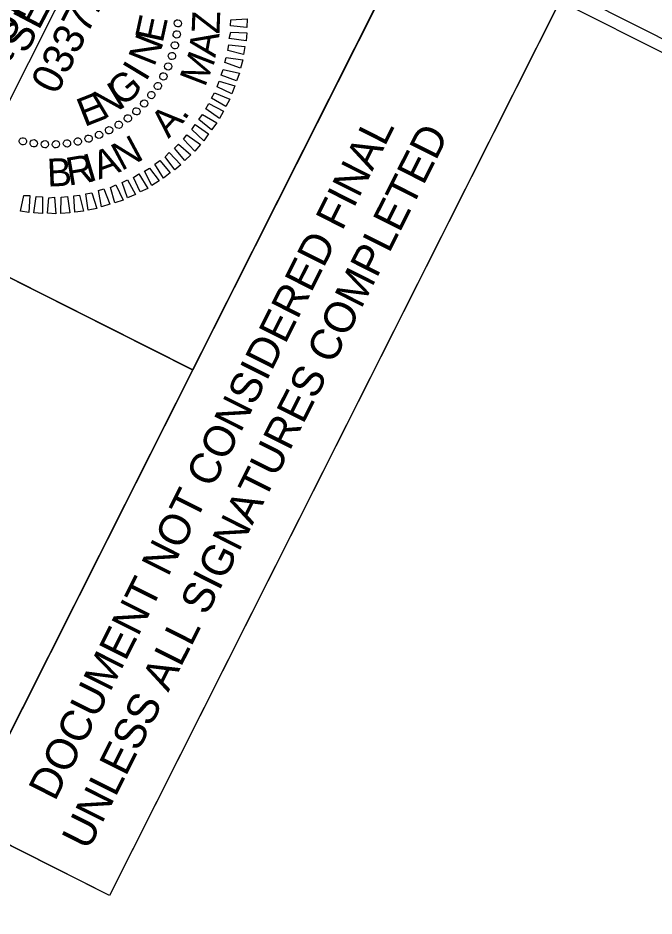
# Model space of a CAD drawing. Extents: x 2010322 to 2012069, y 441674 to 443687.
# Drawn here: x 2011152.3 to 2011277.9, y 443389 to 443566.2 of the extents above; entities that cross this region are included whole.
import ezdxf

# ---------------------------------------------------------------- set-up
doc = ezdxf.new("R2010")
doc.units = 0
for name, color, linetype in [('Sheet Clip Boundary CELL', 7, 'Continuous'), ('Sheet Plan And Profile CELL', 7, 'Continuous'), ('Sheet Professional Seal CELL', 7, 'Continuous'), ('Sheet Profile Grid Minor CELL', 7, 'Continuous'), ('Sheet Sticker Exception Certification CELL', 7, 'Continuous'), ('Sheet Sticker Incomplete CELL', 7, 'Continuous')]:
    doc.layers.add(name, color=color, linetype=linetype)

msp = doc.modelspace()

# ---------------------------------------------------------------- linework, layer by layer
at = {"layer": 'Sheet Clip Boundary CELL'}
msp.add_lwpolyline([(2011359.68, 441843.44), (2012033.06, 443180.92), (2011922.92, 443238.13), (2011759.16, 443078.9), (2011595.22, 443247.25), (2011606.93, 443258.94), (2011612.2, 443362.21), (2011388.82, 443474.46), (2011348.46, 443524.76), (2011259.26, 443569.48), (2011170.42, 443393.01), (2011067.41, 443444.87), (2010977.45, 443266.18), (2010917.88, 443296.17), (2010676.94, 442817.58), (2010544.65, 442554.81), (2010423.28, 442313.75), (2010551.1, 442249.4)], close=True, dxfattribs=at)
at = {"layer": 'Sheet Plan And Profile CELL'}
msp.add_line((2011086.37, 443547.34), (2011186.81, 443496.77), dxfattribs=at)
for points in [[(2011097.8, 443653.54), (2010423.28, 442313.75), (2011361.14, 441841.59), (2012035.65, 443181.38)], [(2011086.37, 443547.34), (2011131.34, 443636.65), (2011231.82, 443586.07), (2011186.86, 443496.75)], [(2011041.38, 443457.97), (2011086.37, 443547.34), (2011186.86, 443496.75), (2011141.87, 443407.38)]]:
    msp.add_lwpolyline(points, close=True, dxfattribs=at)
at = {"layer": 'Sheet Professional Seal CELL'}
for p, q in [((2011183.92, 443565.1), (2011183.92, 443565.1)), ((2011183.74, 443562.96), (2011183.74, 443562.96)), ((2011183.33, 443560.81), (2011183.33, 443560.81)), ((2011182.7, 443558.67), (2011182.7, 443558.67)), ((2011182, 443556.61), (2011182, 443556.61)), ((2011181.05, 443554.62), (2011181.05, 443554.62)), ((2011179.93, 443552.73), (2011179.93, 443552.73)), ((2011178.65, 443550.96), (2011178.65, 443550.96)), ((2011177.31, 443549.29), (2011177.31, 443549.29)), ((2011175.74, 443547.73), (2011175.74, 443547.73)), ((2011174.03, 443546.35), (2011174.03, 443546.35)), ((2011170.34, 443544.01), (2011170.34, 443544.01)), ((2011172.26, 443545.06), (2011172.26, 443545.06)), ((2011153.34, 443541.82), (2011153.34, 443541.82)), ((2011164.16, 443541.75), (2011164.16, 443541.75)), ((2011166.31, 443542.34), (2011166.31, 443542.34)), ((2011168.34, 443543.05), (2011168.34, 443543.05)), ((2011155.48, 443541.41), (2011155.48, 443541.41)), ((2011157.63, 443541.23), (2011157.63, 443541.23)), ((2011159.82, 443541.24), (2011159.82, 443541.24)), ((2011162.03, 443541.42), (2011162.03, 443541.42))]:
    msp.add_line(p, q, dxfattribs=at)
for points in [[(2011194.37, 443565.83), (2011197.59, 443566), (2011197.52, 443564.31), (2011194.27, 443564.65)], [(2011194.32, 443563.4), (2011197.49, 443563.25), (2011197.35, 443561.64), (2011194.02, 443562.15)], [(2011193.93, 443560.85), (2011197.13, 443560.53), (2011196.83, 443558.94), (2011193.77, 443559.75)], [(2011193.43, 443558.41), (2011196.72, 443557.93), (2011196.26, 443556.26), (2011193.18, 443557.36)], [(2011192.84, 443556.02), (2011196.06, 443555.3), (2011195.45, 443553.76), (2011192.44, 443554.88)], [(2011192.03, 443553.74), (2011195.14, 443552.8), (2011194.55, 443551.19), (2011191.63, 443552.6)], [(2011191.13, 443551.4), (2011194.15, 443550.16), (2011193.36, 443548.71), (2011190.55, 443550.35)], [(2011190.01, 443549.28), (2011192.91, 443547.82), (2011192.12, 443546.36), (2011189.42, 443548.23)], [(2011188.75, 443547.11), (2011191.56, 443545.47), (2011190.55, 443544.13), (2011188.03, 443546.13)], [(2011187.31, 443545.15), (2011189.97, 443543.31), (2011189, 443541.95), (2011186.64, 443544.14)], [(2011185.67, 443543.12), (2011188.35, 443541.21), (2011187.23, 443539.87), (2011184.98, 443542.29)], [(2011184.01, 443541.27), (2011186.45, 443539.2), (2011185.3, 443538.04), (2011183.23, 443540.49)], [(2011180.34, 443538.08), (2011182.41, 443535.64), (2011181.09, 443534.57), (2011179.35, 443537.34)], [(2011182.2, 443539.66), (2011184.49, 443537.22), (2011183.33, 443536.24), (2011181.37, 443538.79)], [(2011178.28, 443536.54), (2011180.21, 443534.05), (2011178.78, 443533.1), (2011177.31, 443535.96)], [(2011176.19, 443535.41), (2011178, 443532.54), (2011176.47, 443531.85), (2011175.16, 443534.69)], [(2011171.69, 443533.25), (2011173.09, 443530.25), (2011171.48, 443529.72), (2011170.6, 443532.74)], [(2011173.93, 443534.25), (2011175.56, 443531.36), (2011173.99, 443530.69), (2011172.88, 443533.72)], [(2011154.67, 443531.13), (2011154.46, 443527.82), (2011152.83, 443528.03), (2011153.51, 443531.15)], [(2011162.09, 443530.97), (2011162.6, 443527.75), (2011160.83, 443527.58), (2011160.89, 443530.8)], [(2011164.51, 443531.21), (2011165.28, 443528.08), (2011163.56, 443527.88), (2011163.39, 443531.1)], [(2011166.93, 443531.68), (2011167.9, 443528.61), (2011166.22, 443528.28), (2011165.72, 443531.5)], [(2011169.32, 443532.43), (2011170.45, 443529.45), (2011168.84, 443528.92), (2011168.27, 443532.12)], [(2011157.17, 443530.88), (2011157.19, 443527.57), (2011155.47, 443527.7), (2011155.97, 443530.92)], [(2011159.54, 443530.8), (2011159.85, 443527.51), (2011158.17, 443527.63), (2011158.43, 443530.69)]]:
    msp.add_lwpolyline(points, close=True, dxfattribs=at)
for centre, major_axis in [((2011183.89, 443565.12), (0.719, -0.034)), ((2011183.69, 443562.94), (0.713, -0.097)), ((2011183.3, 443560.79), (0.702, -0.159)), ((2011182.73, 443558.68), (0.686, -0.219)), ((2011181.97, 443556.62), (0.664, -0.278)), ((2011181.04, 443554.65), (0.637, -0.335)), ((2011179.94, 443552.75), (0.606, -0.389)), ((2011178.67, 443550.97), (0.57, -0.441)), ((2011177.26, 443549.3), (0.529, -0.488)), ((2011174.03, 443546.36), (0.436, -0.573)), ((2011175.71, 443547.76), (0.484, -0.533)), ((2011172.23, 443545.11), (0.384, -0.609)), ((2011168.34, 443543.1), (0.273, -0.666)), ((2011170.33, 443544.02), (0.33, -0.64)), ((2011153.31, 443541.85), (-0.159, -0.702)), ((2011155.47, 443541.46), (-0.097, -0.713)), ((2011157.65, 443541.26), (-0.034, -0.719)), ((2011159.83, 443541.25), (0.029, -0.719)), ((2011162.01, 443541.43), (0.091, -0.714)), ((2011164.17, 443541.81), (0.153, -0.704)), ((2011166.29, 443542.36), (0.214, -0.688))]:
    msp.add_ellipse(centre, major_axis=major_axis, ratio=0.999708, dxfattribs=at)
at = {"layer": 'Sheet Sticker Exception Certification CELL'}
for p, q in [((2011141.85, 443407.39), (2011231.81, 443586.07)), ((2011260.37, 443571.69), (2011170.42, 443393.01)), ((2011170.42, 443393.01), (2011141.85, 443407.39))]:
    msp.add_line(p, q, dxfattribs=at)
at = {"layer": 'Sheet Sticker Incomplete CELL'}
msp.add_lwpolyline([(2011103.56, 443456.39), (2011082.57, 443466.96), (2011148.67, 443598.26), (2011169.66, 443587.69)], close=True, dxfattribs=at)

# ---------------------------------------------------------------- texts
at = {"layer": 'Sheet Professional Seal CELL'}
for s, height, rotation, p in [('SEAL', 5.998, 62.277, (2011153.96, 443558.86)), ('E', 5.64, 77.6888, (2011180.89, 443561.09)), ('N', 5.64, 68.3334, (2011179.2, 443556.4)), ('I', 5.64, 58.9782, (2011177.56, 443553.47)), ('G', 5.64, 40.2673, (2011172.92, 443548.47)), ('N', 5.64, 30.911, (2011169.2, 443546.09)), ('E', 5.64, 21.5539, (2011165.44, 443544.63))]:
    msp.add_text(s, height=height, rotation=rotation, dxfattribs=at).set_placement(p)
at = {"layer": 'Sheet Profile Grid Minor CELL'}
for s, height, rotation, p in [('033719', 5.998, 63.277, (2011160, 443550.82)), ('Z', 5.5, 87.7941, (2011192.1, 443562.96)), ('A', 5.5, 79.6083, (2011191.28, 443558.25)), ('M', 5.5, 68.9324, (2011189.23, 443552.38)), ('A', 5.5, 47.5663, (2011182.06, 443542.27)), ('.', 5.5, 55.7521, (2011185.25, 443545.82)), ('N', 5.5, 28.1894, (2011172.77, 443535.93)), ('A', 5.5, 20.0036, (2011168.3, 443534.25)), ('B', 5.5, 2.4299, (2011158.18, 443532.89)), ('R', 5.5, 9.5567, (2011162.33, 443533.07)), ('I', 5.5, 16.4832, (2011166.31, 443533.73))]:
    msp.add_text(s, height=height, rotation=rotation, dxfattribs=at).set_placement(p)
at = {"layer": 'Sheet Sticker Exception Certification CELL'}
for s, p in [('DOCUMENT NOT CONSIDERED FINAL', (2011159.65, 443411.44)), ('UNLESS ALL SIGNATURES COMPLETED', (2011166.24, 443401.71))]:
    msp.add_text(s, height=6.124, rotation=63.277, dxfattribs=at).set_placement(p)
at = {"layer": 'Sheet Sticker Incomplete CELL'}
for s, height, p in [('INCOMPLETE PLANS', 11.52, (2011097.14, 443469.65)), ('DO NOT USE FOR R/W ACQUISITION', 5.76, (2011104.81, 443469.42))]:
    msp.add_text(s, height=height, rotation=63.277, dxfattribs=at).set_placement(p)

doc.saveas('drawing.dxf')
